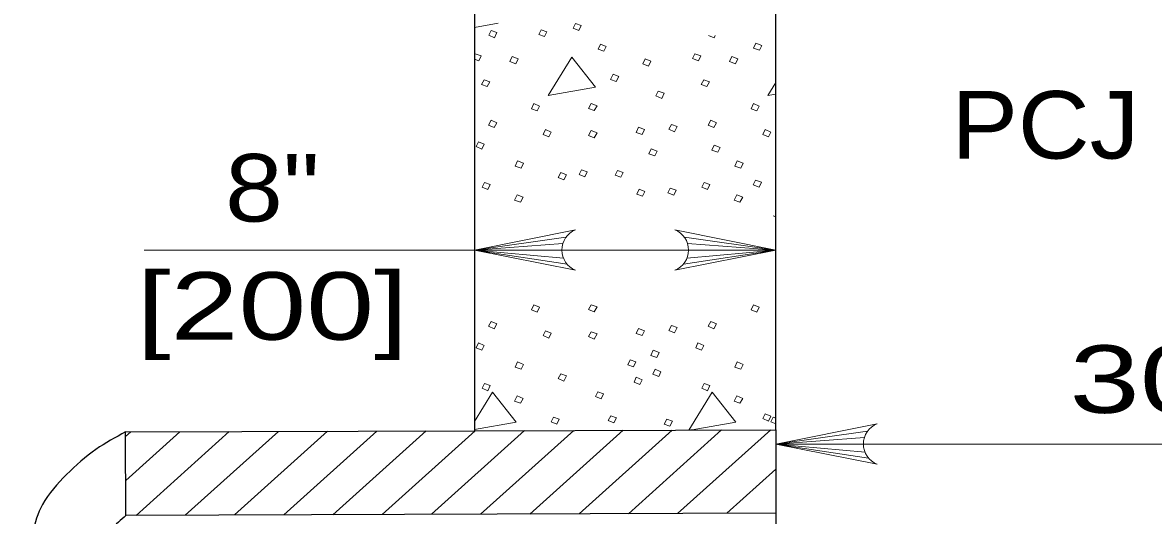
# Model space of a CAD drawing. Extents: x -1431.2 to -1397.2, y -1045.1 to -1001.1.
# Drawn here: x -1427.584 to -1424.925, y -1041.575 to -1040.416 of the extents above; entities that cross this region are included whole.
import ezdxf
from ezdxf.enums import TextEntityAlignment as Align

# ---------------------------------------------------------------- set-up
doc = ezdxf.new("R2010")
doc.units = 0
doc.header["$LTSCALE"] = 0.064
doc.layers.add('1', color=7, linetype='Continuous', lineweight=13)

msp = doc.modelspace()

# ---------------------------------------------------------------- linework, layer by layer
at = {"layer": '1', "lineweight": 25}
for p, q in [((-1426.52183, -1039.1075), (-1426.52183, -1041.37567)), ((-1425.81283, -1041.37325), (-1425.81283, -1040.04383)), ((-1425.81283, -1041.37325), (-1425.81283, -1042.9205))]:
    msp.add_line(p, q, dxfattribs=at)
at = {"layer": '1'}
for p, q in [((-1426.52183, -1040.42717), (-1426.46617, -1040.41742)), ((-1426.52183, -1040.49308), (-1426.52, -1040.48908)), ((-1425.8195, -1040.87075), (-1425.81283, -1040.87308)), ((-1426.30658, -1040.92075), (-1426.52183, -1040.95092)), ((-1426.31392, -1040.93567), (-1426.52183, -1040.95092)), ((-1426.02808, -1040.92075), (-1425.81283, -1040.95092)), ((-1426.02083, -1040.93567), (-1425.81283, -1040.95092)), ((-1425.81283, -1040.95092), (-1427.29867, -1040.95092)), ((-1426.31617, -1040.95092), (-1426.52183, -1040.95092)), ((-1426.31233, -1040.97025), (-1426.52183, -1040.95092)), ((-1426.30408, -1040.98417), (-1426.52183, -1040.95092)), ((-1426.03058, -1040.98417), (-1425.81283, -1040.95092)), ((-1426.02242, -1040.97025), (-1425.81283, -1040.95092)), ((-1426.01858, -1040.95092), (-1425.81283, -1040.95092)), ((-1426.47917, -1041.285), (-1426.52183, -1041.35375)), ((-1425.96267, -1041.285), (-1426.01783, -1041.374)), ((-1425.8195, -1041.34367), (-1425.81283, -1041.34608)), ((-1427.34217, -1041.38908), (-1427.33025, -1041.37842)), ((-1427.34167, -1041.49242), (-1427.2145, -1041.37808)), ((-1427.31767, -1041.57467), (-1427.09875, -1041.37767)), ((-1427.20183, -1041.57425), (-1426.98292, -1041.37725)), ((-1427.08617, -1041.57383), (-1426.86717, -1041.37683)), ((-1426.97033, -1041.57342), (-1426.75142, -1041.3765)), ((-1426.85458, -1041.57308), (-1426.63567, -1041.37608)), ((-1426.73883, -1041.57267), (-1426.51983, -1041.37567)), ((-1426.623, -1041.57225), (-1426.40408, -1041.37525)), ((-1426.50725, -1041.57192), (-1426.28833, -1041.37483)), ((-1426.39142, -1041.5715), (-1426.1725, -1041.37442)), ((-1426.27567, -1041.57108), (-1426.05667, -1041.374)), ((-1426.15992, -1041.57075), (-1425.941, -1041.37367)), ((-1426.04408, -1041.57033), (-1425.82517, -1041.37333)), ((-1426.01367, -1041.37392), (-1426.01358, -1041.37392)), ((-1426.01358, -1041.37392), (-1426.0135, -1041.37392)), ((-1426.0135, -1041.37392), (-1426.01342, -1041.37392)), ((-1426.01342, -1041.37392), (-1426.01333, -1041.37392)), ((-1426.01333, -1041.37392), (-1426.01308, -1041.37392)), ((-1426.01308, -1041.37392), (-1426.01292, -1041.37392)), ((-1426.01292, -1041.37392), (-1426.01275, -1041.37392)), ((-1426.01275, -1041.37392), (-1426.01258, -1041.37392)), ((-1426.01258, -1041.37392), (-1426.01242, -1041.37392)), ((-1426.01242, -1041.37392), (-1426.01225, -1041.37392)), ((-1426.01225, -1041.37392), (-1426.012, -1041.37392)), ((-1426.012, -1041.37392), (-1426.01183, -1041.37392)), ((-1426.01183, -1041.37392), (-1426.01167, -1041.37392)), ((-1426.01167, -1041.37392), (-1426.0115, -1041.37392)), ((-1426.0115, -1041.37392), (-1426.01133, -1041.37392)), ((-1426.01133, -1041.37392), (-1426.01117, -1041.37392)), ((-1426.01117, -1041.37392), (-1426.01092, -1041.37392)), ((-1426.01092, -1041.37392), (-1426.01075, -1041.37392)), ((-1426.01075, -1041.37392), (-1426.01058, -1041.37392)), ((-1426.01058, -1041.37392), (-1426.01042, -1041.37392)), ((-1426.01042, -1041.37392), (-1426.01025, -1041.37392)), ((-1426.01025, -1041.37392), (-1426.01008, -1041.37392)), ((-1426.01008, -1041.37392), (-1426.00983, -1041.37392)), ((-1426.00983, -1041.37392), (-1426.00967, -1041.37392)), ((-1425.59767, -1041.37675), (-1425.81283, -1041.40692)), ((-1425.60492, -1041.39167), (-1425.81283, -1041.40692)), ((-1423.9725, -1041.40692), (-1425.81283, -1041.40692)), ((-1425.60717, -1041.40692), (-1425.81283, -1041.40692)), ((-1425.60333, -1041.42625), (-1425.81283, -1041.40692)), ((-1425.59508, -1041.44017), (-1425.81283, -1041.40692)), ((-1425.92833, -1041.56992), (-1425.81283, -1041.46592))]:
    msp.add_line(p, q, dxfattribs=at)
for points in [[(-1426.48275, -1040.43442), (-1426.46917, -1040.43933), (-1426.47467, -1040.45158), (-1426.48825, -1040.44583)], [(-1426.36533, -1040.43267), (-1426.35175, -1040.43758), (-1426.35717, -1040.449), (-1426.37075, -1040.44417)], [(-1426.28433, -1040.418), (-1426.27075, -1040.42292), (-1426.27617, -1040.43433), (-1426.28975, -1040.42942)], [(-1426.22542, -1040.46708), (-1426.21183, -1040.472), (-1426.21725, -1040.48342), (-1426.23092, -1040.4785)], [(-1425.85983, -1040.46458), (-1425.84625, -1040.4695), (-1425.85167, -1040.48092), (-1425.86525, -1040.476)], [(-1426.433, -1040.49558), (-1426.41933, -1040.50133), (-1426.42483, -1040.51275), (-1426.43842, -1040.50783)], [(-1426.2925, -1040.49725), (-1426.34867, -1040.58775), (-1426.23725, -1040.56817)], [(-1426.12033, -1040.50133), (-1426.10675, -1040.507), (-1426.11217, -1040.51842), (-1426.12575, -1040.51275)], [(-1426.00342, -1040.48908), (-1425.98983, -1040.494), (-1425.99525, -1040.50625), (-1426.00883, -1040.5005)], [(-1425.91642, -1040.49558), (-1425.90283, -1040.50133), (-1425.90825, -1040.51275), (-1425.92183, -1040.50783)], [(-1426.1955, -1040.53717), (-1426.18192, -1040.54292), (-1426.18825, -1040.55433), (-1426.20192, -1040.54942)], [(-1426.49908, -1040.55025), (-1426.4855, -1040.55517), (-1426.49183, -1040.56658), (-1426.50542, -1040.56167)], [(-1425.98258, -1040.55025), (-1425.969, -1040.55517), (-1425.97533, -1040.56658), (-1425.98892, -1040.56167)], [(-1426.0895, -1040.57717), (-1426.07592, -1040.58208), (-1426.08133, -1040.59425), (-1426.09492, -1040.58858)], [(-1426.38225, -1040.6065), (-1426.36858, -1040.61225), (-1426.37408, -1040.62367), (-1426.38767, -1040.61875)], [(-1426.24717, -1040.6065), (-1426.23358, -1040.61142), (-1426.23992, -1040.62283), (-1426.2535, -1040.61792)], [(-1425.86567, -1040.6065), (-1425.85208, -1040.61225), (-1425.8575, -1040.62367), (-1425.87108, -1040.61875)], [(-1426.48275, -1040.64567), (-1426.46917, -1040.65133), (-1426.47558, -1040.66275), (-1426.48917, -1040.65708)], [(-1425.96625, -1040.64567), (-1425.95267, -1040.65133), (-1425.959, -1040.66275), (-1425.97258, -1040.65708)], [(-1426.355, -1040.66767), (-1426.34142, -1040.67342), (-1426.34692, -1040.68483), (-1426.3605, -1040.67908)], [(-1426.24717, -1040.67008), (-1426.23358, -1040.675), (-1426.23992, -1040.68725), (-1426.2535, -1040.6815)], [(-1426.13575, -1040.662), (-1426.12217, -1040.66767), (-1426.12758, -1040.67908), (-1426.14117, -1040.67417)], [(-1426.05867, -1040.65542), (-1426.04508, -1040.66033), (-1426.05142, -1040.67258), (-1426.06508, -1040.66683)], [(-1425.8385, -1040.66767), (-1425.82492, -1040.67342), (-1425.83033, -1040.68483), (-1425.84392, -1040.67908)], [(-1426.51267, -1040.69625), (-1426.49908, -1040.70192), (-1426.50458, -1040.71333), (-1426.51817, -1040.70767)], [(-1426.106, -1040.71317), (-1426.09242, -1040.71808), (-1426.09783, -1040.7295), (-1426.11142, -1040.72458)], [(-1425.95783, -1040.70458), (-1425.94425, -1040.7095), (-1425.94967, -1040.72092), (-1425.96325, -1040.716)], [(-1426.42025, -1040.74108), (-1426.40667, -1040.74675), (-1426.41208, -1040.75817), (-1426.42575, -1040.75333)], [(-1425.90375, -1040.74108), (-1425.89017, -1040.74675), (-1425.89558, -1040.75817), (-1425.90917, -1040.75333)], [(-1426.31875, -1040.76883), (-1426.30517, -1040.77367), (-1426.3115, -1040.78592), (-1426.32508, -1040.78017)], [(-1426.27008, -1040.762), (-1426.25642, -1040.76692), (-1426.26192, -1040.77833), (-1426.2755, -1040.77342)], [(-1426.18558, -1040.76342), (-1426.172, -1040.76833), (-1426.1775, -1040.77975), (-1426.19108, -1040.77483)], [(-1426.49817, -1040.79167), (-1426.48458, -1040.7965), (-1426.49008, -1040.80875), (-1426.50367, -1040.80308)], [(-1426.06133, -1040.80508), (-1426.04775, -1040.81), (-1426.05325, -1040.82142), (-1426.06683, -1040.8165)], [(-1425.98167, -1040.79167), (-1425.96808, -1040.7965), (-1425.9735, -1040.80875), (-1425.98708, -1040.80308)], [(-1425.86067, -1040.78642), (-1425.84708, -1040.79133), (-1425.8525, -1040.80275), (-1425.86608, -1040.79783)], [(-1426.42117, -1040.821), (-1426.40758, -1040.82667), (-1426.41392, -1040.83808), (-1426.4275, -1040.83325)], [(-1426.13467, -1040.808), (-1426.12108, -1040.81283), (-1426.1265, -1040.82425), (-1426.14008, -1040.81933)], [(-1425.90467, -1040.821), (-1425.89108, -1040.82667), (-1425.89742, -1040.83808), (-1425.911, -1040.83325)], [(-1426.38225, -1041.0795), (-1426.36858, -1041.08517), (-1426.37408, -1041.09658), (-1426.38767, -1041.09175)], [(-1426.24717, -1041.0795), (-1426.23358, -1041.08442), (-1426.23992, -1041.09583), (-1426.2535, -1041.09092)], [(-1425.86567, -1041.0795), (-1425.85208, -1041.08517), (-1425.8575, -1041.09658), (-1425.87108, -1041.09175)], [(-1426.48275, -1041.11867), (-1426.46917, -1041.12433), (-1426.47558, -1041.13575), (-1426.48917, -1041.13008)], [(-1425.96625, -1041.11867), (-1425.95267, -1041.12433), (-1425.959, -1041.13575), (-1425.97258, -1041.13008)], [(-1426.355, -1041.14067), (-1426.34142, -1041.14633), (-1426.34692, -1041.15775), (-1426.3605, -1041.15208)], [(-1426.24717, -1041.14308), (-1426.23358, -1041.148), (-1426.23992, -1041.16025), (-1426.2535, -1041.1545)], [(-1426.13575, -1041.13492), (-1426.12217, -1041.14067), (-1426.12758, -1041.15208), (-1426.14117, -1041.14717)], [(-1426.05867, -1041.12842), (-1426.04508, -1041.13333), (-1426.05142, -1041.14558), (-1426.06508, -1041.13983)], [(-1426.51267, -1041.16917), (-1426.49908, -1041.17492), (-1426.50458, -1041.18633), (-1426.51817, -1041.18058)], [(-1425.99617, -1041.16917), (-1425.98258, -1041.17492), (-1425.988, -1041.18633), (-1426.00158, -1041.18058)], [(-1426.10125, -1041.18633), (-1426.08767, -1041.192), (-1426.09317, -1041.20342), (-1426.10675, -1041.19858)], [(-1426.42025, -1041.21408), (-1426.40667, -1041.21975), (-1426.41208, -1041.23117), (-1426.42575, -1041.22625)], [(-1426.15567, -1041.20917), (-1426.14208, -1041.21408), (-1426.1475, -1041.2255), (-1426.16108, -1041.22058)], [(-1426.09675, -1041.23117), (-1426.08317, -1041.23692), (-1426.08858, -1041.24833), (-1426.10217, -1041.24258)], [(-1425.90375, -1041.21408), (-1425.89017, -1041.21975), (-1425.89558, -1041.23117), (-1425.90917, -1041.22625)], [(-1426.31875, -1041.24175), (-1426.30517, -1041.24667), (-1426.3115, -1041.25892), (-1426.32508, -1041.25317)], [(-1426.14117, -1041.24992), (-1426.12758, -1041.25567), (-1426.133, -1041.26708), (-1426.14658, -1041.26133)], [(-1426.49817, -1041.26458), (-1426.48458, -1041.2695), (-1426.49008, -1041.28175), (-1426.50367, -1041.276)], [(-1426.23175, -1041.28417), (-1426.21817, -1041.28908), (-1426.22367, -1041.3005), (-1426.23725, -1041.29558)], [(-1425.98167, -1041.26458), (-1425.96808, -1041.2695), (-1425.9735, -1041.28175), (-1425.98708, -1041.276)], [(-1426.42117, -1041.294), (-1426.40758, -1041.29967), (-1426.41392, -1041.31108), (-1426.4275, -1041.30617)], [(-1425.90467, -1041.294), (-1425.89108, -1041.29967), (-1425.89742, -1041.31108), (-1425.911, -1041.30617)], [(-1425.8385, -1041.33567), (-1425.82492, -1041.34142), (-1425.83033, -1041.35283), (-1425.84392, -1041.34708)], [(-1426.336, -1041.34367), (-1426.32242, -1041.34858), (-1426.32783, -1041.36), (-1426.34142, -1041.35508)], [(-1426.201, -1041.34042), (-1426.18742, -1041.34533), (-1426.19375, -1041.35675), (-1426.20733, -1041.35183)], [(-1426.06958, -1041.34858), (-1426.056, -1041.3535), (-1426.06233, -1041.36492), (-1426.07592, -1041.36)]]:
    msp.add_lwpolyline(points, close=True, dxfattribs=at)
for points in [[(-1425.95567, -1040.44608), (-1425.95808, -1040.45158), (-1425.97125, -1040.44608)], [(-1426.52, -1040.48908), (-1426.50633, -1040.494), (-1426.51183, -1040.50625), (-1426.52183, -1040.502)], [(-1425.81283, -1040.55667), (-1425.83217, -1040.58775), (-1425.81283, -1040.58433)], [(-1426.28408, -1040.99842), (-1426.52183, -1040.95092), (-1426.28408, -1040.90333)], [(-1426.05058, -1040.99842), (-1425.81283, -1040.95092), (-1426.05058, -1040.90333)], [(-1426.52183, -1041.37317), (-1426.42392, -1041.35592), (-1426.47917, -1041.285)], [(-1426.00967, -1041.37392), (-1425.90733, -1041.35592), (-1425.96267, -1041.285)], [(-1425.81283, -1041.35942), (-1425.82492, -1041.35508), (-1425.8195, -1041.34367)], [(-1425.57508, -1041.45442), (-1425.81283, -1041.40692), (-1425.57508, -1041.35933)]]:
    msp.add_lwpolyline(points, dxfattribs=at)
at = {"layer": '1', "lineweight": 25}
for points in [[(-1427.34217, -1041.37842), (-1426.52183, -1041.37567), (-1425.81283, -1041.37325)], [(-1425.81283, -1041.5695), (-1427.34133, -1041.57475), (-1427.34217, -1041.37842)]]:
    msp.add_lwpolyline(points, dxfattribs=at)
at = {"layer": '1'}
for centre, start, end in [((-1426.26492, -1040.95084), 112.08782, 247.91395), ((-1426.06979, -1040.95084), 292.08605, 67.91218), ((-1425.55593, -1041.40683), 112.08782, 247.91395)]:
    msp.add_arc(centre, 0.05131, start, end, dxfattribs=at)
at = {"layer": '1', "lineweight": 25}
for points in [[(-1427.34217, -1041.37842), (-1427.41192, -1041.41958), (-1427.48092, -1041.4785), (-1427.53742, -1041.54925), (-1427.57258, -1041.68775), (-1427.58175, -1041.81825), (-1427.53158, -1041.99925), (-1427.45192, -1042.15033), (-1427.3535, -1042.28683), (-1427.29508, -1042.37942), (-1427.22783, -1042.51233), (-1427.20967, -1042.62008), (-1427.21758, -1042.74533), (-1427.25408, -1042.84058), (-1427.28942, -1042.88325), (-1427.3355, -1042.92575)], [(-1427.34133, -1041.57475), (-1427.376, -1041.60775), (-1427.41483, -1041.664), (-1427.44242, -1041.74783), (-1427.45992, -1041.86558), (-1427.458, -1041.9805), (-1427.42217, -1042.12125), (-1427.35525, -1042.284)]]:
    msp.add_spline(points, degree=3, dxfattribs=at)

# ---------------------------------------------------------------- texts
at = {"layer": '1'}
for s, width, p in [('PCJ', 1.1, (-1425.39967, -1040.73575)), ('30" [750]', 1.4, (-1425.12258, -1041.33375))]:
    msp.add_text(s, height=0.1588, dxfattribs=dict(at, width=width)).set_placement(p)
for s, width, p in [('8"', 1.15, (-1426.997, -1040.88383)), ('[200]', 1.35, (-1426.99704, -1041.16167))]:
    msp.add_text(s, height=0.1588, dxfattribs=dict(at, width=width)).set_placement(p, align=Align.CENTER)

doc.saveas('drawing.dxf')
